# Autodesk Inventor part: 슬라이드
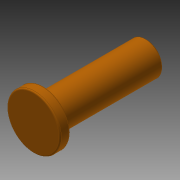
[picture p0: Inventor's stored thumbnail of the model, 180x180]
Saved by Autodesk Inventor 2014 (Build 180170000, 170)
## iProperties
Company: 한국ATC센터
Created: 2015-11
Part Number: 슬라이드
Document SubType Name: Modeling
Designer: mdu
Density: 7.86 g/cm^3
Material: 강철, 연강
Mass: 53.0481 g
Surface Area: 25.6984 cm^2
Volume: 6.74912 cm^3
Appearance: 진회색
Author: mdu
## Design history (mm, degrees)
sketch "스케치1"
  geometry: L1 (13.5, 41)-(13.5, 74) reference; L2 (13.5, 74)-(26.5, 74) reference; L3 (20, 74)-(20, 29); L4 (20, 74)-(13.5, 74); L5 (13.5, 74)-(13.5, 33); L6 (13.5, 33)-(9.5, 33); L7 (9.5, 33)-(9.5, 29); L8 (20, 73.5)-(13.5, 73.5); L9 (20, 29)-(9.5, 29); 1 further point
  constraints: 16 end point, 4 perpendicular, 3 point on line, 1 collinear, 1 midpoint, 1 parallel, 1 vertical, 2 other
  dimensions: "d0" = 45 distance of L3.start L3.end; "d1" = 21 diameter of L7 L3; "d2" = 4 distance from line of L3.end L6; "d4" = 0.5 distance between parallel lines of L8 L2
revolve "회전1" sketch "스케치1" stored, may be unused: angle "d5" = 90 deg
fillet "모깎기1" dims "d6" = 0.5
chamfer "모따기1" distance "d9" = 0.5; stored, may be unused: second distance "d10" = 2, angle "d11" = 45 deg
node "솔리드1"
node "참조1"
